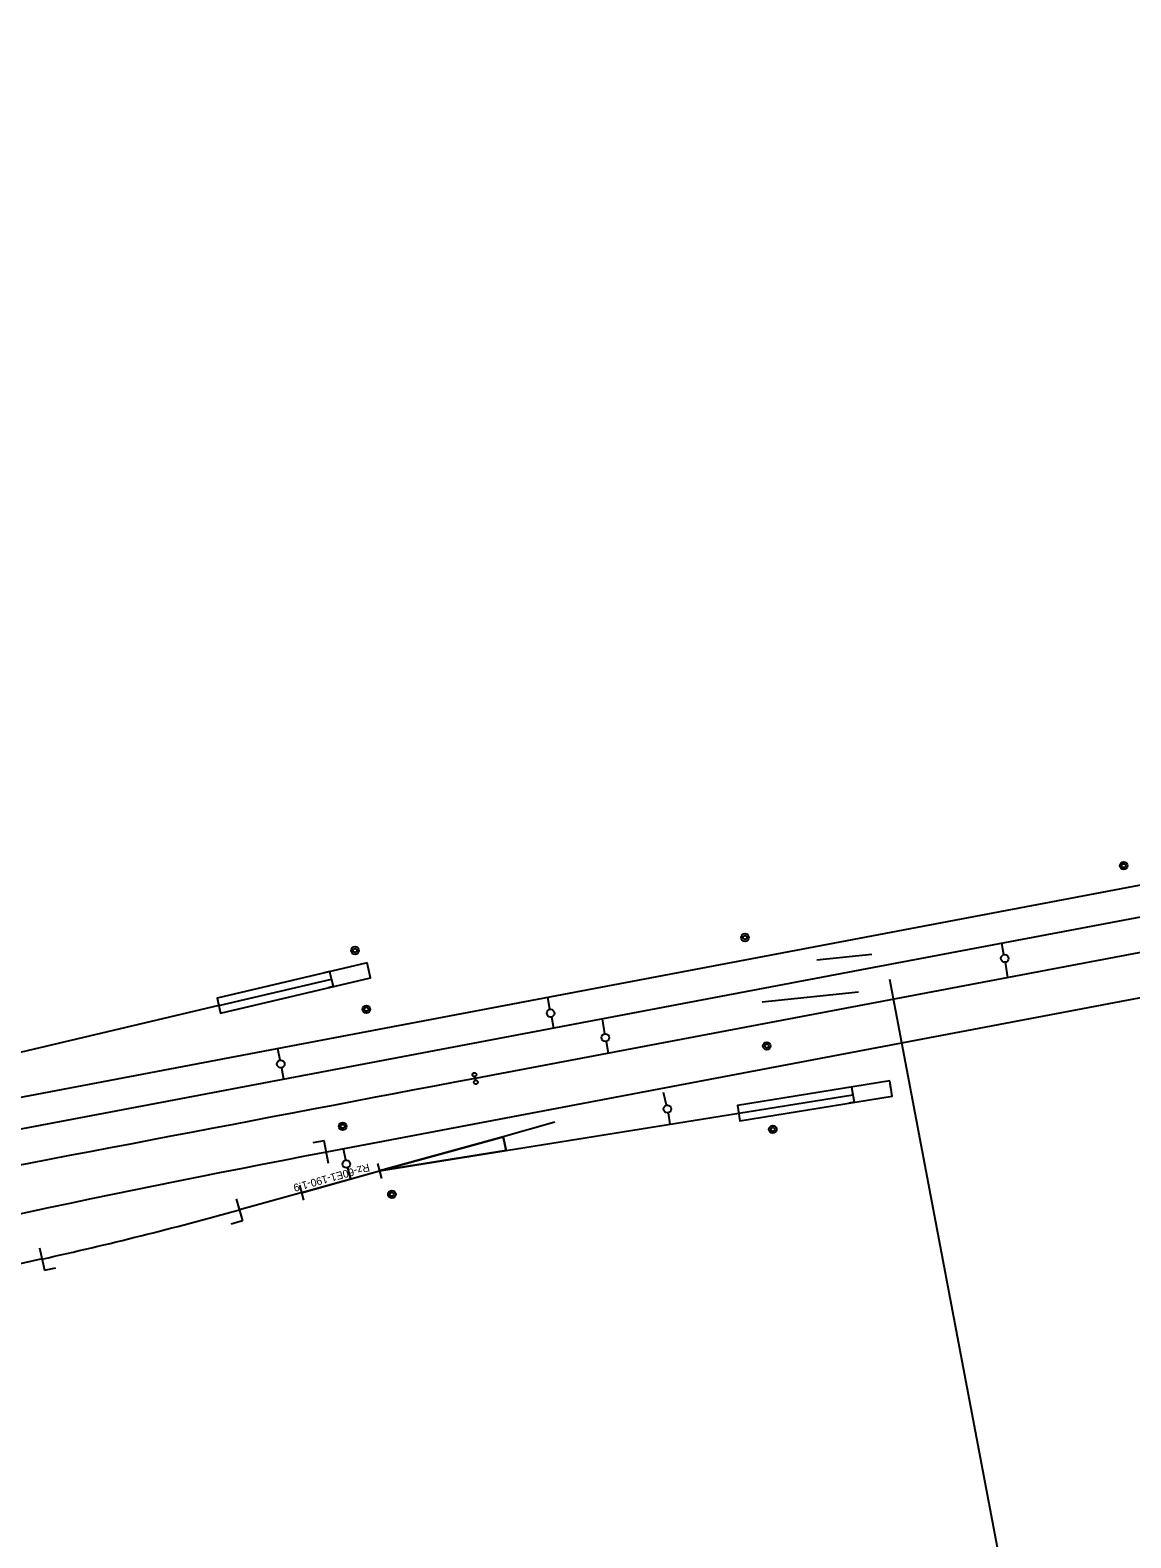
# Model space of a CAD drawing. Extents: x 6540402 to 6566579, y 5525343 to 5532423.
# Drawn here: x 6558463 to 6558605.8, y 5528817.7 to 5529013.3 of the extents above; entities that cross this region are included whole.
import ezdxf

# ---------------------------------------------------------------- set-up
doc = ezdxf.new("R2010")
doc.units = 0
for name, color, linetype in [('IR_ps_geometria', 7, 'Continuous'), ('T_plan_koziol oporowy', 7, 'Continuous'), ('TOR_PS_ODW-studnie betonowe', 7, 'Continuous'), ('TOR_PS_OPIS_T-opisy dodatkowe', 7, 'Continuous'), ('TOR_PS_OPIS_T-symbole geometrii', 7, 'Continuous'), ('TOR_PS_OPIS_T-ukresy', 7, 'Continuous'), ('TOR_PS_T-rozjazdy projektowane', 7, 'Continuous'), ('TOR_PS_T-tory projektowane', 7, 'Continuous'), ('TOR_PS_T-wypelnienia', 7, 'Continuous')]:
    doc.layers.add(name, color=color, linetype=linetype)

# ---------------------------------------------------------------- blocks, each defined once
blk = doc.blocks.new('koziol 15+5')
at = {"layer": 'T_plan_koziol oporowy'}
for p, q in [((15, 1), (14.3, 1)), ((15, 1), (15, -1)), ((20, 0), (20, 1)), ((0, 0), (15, 0)), ((15, -1), (14.3, -1))]:
    blk.add_line(p, q, dxfattribs=at)
blk.add_lwpolyline([(20, 1), (0, 1), (0, -1), (20, -1)], close=True, dxfattribs=at)

msp = doc.modelspace()

# ---------------------------------------------------------------- linework, layer by layer
at = {"layer": 'IR_ps_geometria'}
msp.add_lwpolyline([(6558520.71, 5528877.32), (6558520.76, 5528877.08), (6558520.79, 5528877.08), (6558520.82, 5528877.08), (6558520.86, 5528877.08), (6558520.89, 5528877.07), (6558520.92, 5528877.05), (6558520.95, 5528877.04), (6558520.97, 5528877.02), (6558520.99, 5528876.99), (6558521.01, 5528876.97), (6558521.03, 5528876.94), (6558521.04, 5528876.91), (6558521.05, 5528876.88), (6558521.05, 5528876.85), (6558521.05, 5528876.81), (6558521.05, 5528876.78), (6558521.04, 5528876.75), (6558521.03, 5528876.72), (6558521.01, 5528876.69), (6558520.99, 5528876.66), (6558520.97, 5528876.64), (6558520.94, 5528876.62), (6558520.91, 5528876.61), (6558520.88, 5528876.59), (6558520.85, 5528876.59), (6558520.82, 5528876.58), (6558520.79, 5528876.58), (6558520.75, 5528876.59), (6558520.72, 5528876.6), (6558520.69, 5528876.61), (6558520.66, 5528876.62), (6558520.64, 5528876.64), (6558520.62, 5528876.67), (6558520.6, 5528876.69), (6558520.58, 5528876.72), (6558520.57, 5528876.75), (6558520.56, 5528876.78), (6558520.56, 5528876.82), (6558520.56, 5528876.85), (6558520.56, 5528876.88), (6558520.57, 5528876.91), (6558520.58, 5528876.94), (6558520.6, 5528876.97), (6558520.62, 5528877), (6558520.64, 5528877.02), (6558520.67, 5528877.04), (6558520.7, 5528877.06), (6558520.73, 5528877.07), (6558520.76, 5528877.08), (6558520.67, 5528877.57), (6558520.63, 5528877.56), (6558520.6, 5528877.56), (6558520.57, 5528877.57), (6558520.54, 5528877.58), (6558520.51, 5528877.59), (6558520.48, 5528877.61), (6558520.45, 5528877.63), (6558520.43, 5528877.65), (6558520.41, 5528877.68), (6558520.39, 5528877.7), (6558520.38, 5528877.74), (6558520.37, 5528877.77), (6558520.37, 5528877.8), (6558520.37, 5528877.83), (6558520.37, 5528877.86), (6558520.38, 5528877.9), (6558520.4, 5528877.93), (6558520.41, 5528877.95), (6558520.43, 5528877.98), (6558520.46, 5528878), (6558520.48, 5528878.02), (6558520.51, 5528878.04), (6558520.54, 5528878.05), (6558520.57, 5528878.06), (6558520.6, 5528878.06), (6558520.64, 5528878.06), (6558520.67, 5528878.06), (6558520.7, 5528878.05), (6558520.73, 5528878.04), (6558520.76, 5528878.02), (6558520.79, 5528878), (6558520.81, 5528877.98), (6558520.83, 5528877.95), (6558520.84, 5528877.92), (6558520.86, 5528877.89), (6558520.86, 5528877.86), (6558520.87, 5528877.83), (6558520.87, 5528877.79), (6558520.86, 5528877.76), (6558520.85, 5528877.73), (6558520.84, 5528877.7), (6558520.83, 5528877.67), (6558520.81, 5528877.65), (6558520.78, 5528877.62), (6558520.76, 5528877.6), (6558520.73, 5528877.59), (6558520.7, 5528877.58), (6558520.67, 5528877.57)], close=True, dxfattribs=at)
msp.add_lwpolyline([(6558520.71, 5528877.32), (6558520.76, 5528877.08), (6558520.79, 5528877.08), (6558520.82, 5528877.08), (6558520.86, 5528877.08), (6558520.89, 5528877.07), (6558520.92, 5528877.05), (6558520.95, 5528877.04), (6558520.97, 5528877.02), (6558520.99, 5528876.99), (6558521.01, 5528876.97), (6558521.03, 5528876.94), (6558521.04, 5528876.91), (6558521.05, 5528876.88), (6558521.05, 5528876.85), (6558521.05, 5528876.81), (6558521.05, 5528876.78), (6558521.04, 5528876.75), (6558521.03, 5528876.72), (6558521.01, 5528876.69), (6558520.99, 5528876.66), (6558520.97, 5528876.64), (6558520.94, 5528876.62), (6558520.91, 5528876.61), (6558520.88, 5528876.59), (6558520.85, 5528876.59), (6558520.82, 5528876.58), (6558520.79, 5528876.58), (6558520.75, 5528876.59), (6558520.72, 5528876.6), (6558520.69, 5528876.61), (6558520.66, 5528876.62), (6558520.64, 5528876.64), (6558520.62, 5528876.67), (6558520.6, 5528876.69), (6558520.58, 5528876.72), (6558520.57, 5528876.75), (6558520.56, 5528876.78), (6558520.56, 5528876.82), (6558520.56, 5528876.85), (6558520.56, 5528876.88), (6558520.57, 5528876.91), (6558520.58, 5528876.94), (6558520.6, 5528876.97), (6558520.62, 5528877), (6558520.64, 5528877.02), (6558520.67, 5528877.04), (6558520.7, 5528877.06), (6558520.73, 5528877.07), (6558520.76, 5528877.08), (6558520.67, 5528877.57), (6558520.63, 5528877.56), (6558520.6, 5528877.56), (6558520.57, 5528877.57), (6558520.54, 5528877.58), (6558520.51, 5528877.59), (6558520.48, 5528877.61), (6558520.45, 5528877.63), (6558520.43, 5528877.65), (6558520.41, 5528877.68), (6558520.39, 5528877.7), (6558520.38, 5528877.74), (6558520.37, 5528877.77), (6558520.37, 5528877.8), (6558520.37, 5528877.83), (6558520.37, 5528877.86), (6558520.38, 5528877.9), (6558520.4, 5528877.93), (6558520.41, 5528877.95), (6558520.43, 5528877.98), (6558520.46, 5528878), (6558520.48, 5528878.02), (6558520.51, 5528878.04), (6558520.54, 5528878.05), (6558520.57, 5528878.06), (6558520.6, 5528878.06), (6558520.64, 5528878.06), (6558520.67, 5528878.06), (6558520.7, 5528878.05), (6558520.73, 5528878.04), (6558520.76, 5528878.02), (6558520.79, 5528878), (6558520.81, 5528877.98), (6558520.83, 5528877.95), (6558520.84, 5528877.92), (6558520.86, 5528877.89), (6558520.86, 5528877.86), (6558520.87, 5528877.83), (6558520.87, 5528877.79), (6558520.86, 5528877.76), (6558520.85, 5528877.73), (6558520.84, 5528877.7), (6558520.83, 5528877.67), (6558520.81, 5528877.65), (6558520.78, 5528877.62), (6558520.76, 5528877.6), (6558520.73, 5528877.59), (6558520.7, 5528877.58), (6558520.67, 5528877.57)], close=True, dxfattribs=at)
msp.add_lwpolyline([(6558520.71, 5528877.32), (6558520.76, 5528877.08), (6558520.79, 5528877.08), (6558520.82, 5528877.08), (6558520.86, 5528877.08), (6558520.89, 5528877.07), (6558520.92, 5528877.05), (6558520.95, 5528877.04), (6558520.97, 5528877.02), (6558520.99, 5528876.99), (6558521.01, 5528876.97), (6558521.03, 5528876.94), (6558521.04, 5528876.91), (6558521.05, 5528876.88), (6558521.05, 5528876.85), (6558521.05, 5528876.81), (6558521.05, 5528876.78), (6558521.04, 5528876.75), (6558521.03, 5528876.72), (6558521.01, 5528876.69), (6558520.99, 5528876.66), (6558520.97, 5528876.64), (6558520.94, 5528876.62), (6558520.91, 5528876.61), (6558520.88, 5528876.59), (6558520.85, 5528876.59), (6558520.82, 5528876.58), (6558520.79, 5528876.58), (6558520.75, 5528876.59), (6558520.72, 5528876.6), (6558520.69, 5528876.61), (6558520.66, 5528876.62), (6558520.64, 5528876.64), (6558520.62, 5528876.67), (6558520.6, 5528876.69), (6558520.58, 5528876.72), (6558520.57, 5528876.75), (6558520.56, 5528876.78), (6558520.56, 5528876.82), (6558520.56, 5528876.85), (6558520.56, 5528876.88), (6558520.57, 5528876.91), (6558520.58, 5528876.94), (6558520.6, 5528876.97), (6558520.62, 5528877), (6558520.64, 5528877.02), (6558520.67, 5528877.04), (6558520.7, 5528877.06), (6558520.73, 5528877.07), (6558520.76, 5528877.08), (6558520.67, 5528877.57), (6558520.63, 5528877.56), (6558520.6, 5528877.56), (6558520.57, 5528877.57), (6558520.54, 5528877.58), (6558520.51, 5528877.59), (6558520.48, 5528877.61), (6558520.45, 5528877.63), (6558520.43, 5528877.65), (6558520.41, 5528877.68), (6558520.39, 5528877.7), (6558520.38, 5528877.74), (6558520.37, 5528877.77), (6558520.37, 5528877.8), (6558520.37, 5528877.83), (6558520.37, 5528877.86), (6558520.38, 5528877.9), (6558520.4, 5528877.93), (6558520.41, 5528877.95), (6558520.43, 5528877.98), (6558520.46, 5528878), (6558520.48, 5528878.02), (6558520.51, 5528878.04), (6558520.54, 5528878.05), (6558520.57, 5528878.06), (6558520.6, 5528878.06), (6558520.64, 5528878.06), (6558520.67, 5528878.06), (6558520.7, 5528878.05), (6558520.73, 5528878.04), (6558520.76, 5528878.02), (6558520.79, 5528878), (6558520.81, 5528877.98), (6558520.83, 5528877.95), (6558520.84, 5528877.92), (6558520.86, 5528877.89), (6558520.86, 5528877.86), (6558520.87, 5528877.83), (6558520.87, 5528877.79), (6558520.86, 5528877.76), (6558520.85, 5528877.73), (6558520.84, 5528877.7), (6558520.83, 5528877.67), (6558520.81, 5528877.65), (6558520.78, 5528877.62), (6558520.76, 5528877.6), (6558520.73, 5528877.59), (6558520.7, 5528877.58), (6558520.67, 5528877.57)], close=True, dxfattribs=at)
msp.add_lwpolyline([(6558520.71, 5528877.32), (6558520.76, 5528877.08), (6558520.79, 5528877.08), (6558520.82, 5528877.08), (6558520.86, 5528877.08), (6558520.89, 5528877.07), (6558520.92, 5528877.05), (6558520.95, 5528877.04), (6558520.97, 5528877.02), (6558520.99, 5528876.99), (6558521.01, 5528876.97), (6558521.03, 5528876.94), (6558521.04, 5528876.91), (6558521.05, 5528876.88), (6558521.05, 5528876.85), (6558521.05, 5528876.81), (6558521.05, 5528876.78), (6558521.04, 5528876.75), (6558521.03, 5528876.72), (6558521.01, 5528876.69), (6558520.99, 5528876.66), (6558520.97, 5528876.64), (6558520.94, 5528876.62), (6558520.91, 5528876.61), (6558520.88, 5528876.59), (6558520.85, 5528876.59), (6558520.82, 5528876.58), (6558520.79, 5528876.58), (6558520.75, 5528876.59), (6558520.72, 5528876.6), (6558520.69, 5528876.61), (6558520.66, 5528876.62), (6558520.64, 5528876.64), (6558520.62, 5528876.67), (6558520.6, 5528876.69), (6558520.58, 5528876.72), (6558520.57, 5528876.75), (6558520.56, 5528876.78), (6558520.56, 5528876.82), (6558520.56, 5528876.85), (6558520.56, 5528876.88), (6558520.57, 5528876.91), (6558520.58, 5528876.94), (6558520.6, 5528876.97), (6558520.62, 5528877), (6558520.64, 5528877.02), (6558520.67, 5528877.04), (6558520.7, 5528877.06), (6558520.73, 5528877.07), (6558520.76, 5528877.08), (6558520.67, 5528877.57), (6558520.63, 5528877.56), (6558520.6, 5528877.56), (6558520.57, 5528877.57), (6558520.54, 5528877.58), (6558520.51, 5528877.59), (6558520.48, 5528877.61), (6558520.45, 5528877.63), (6558520.43, 5528877.65), (6558520.41, 5528877.68), (6558520.39, 5528877.7), (6558520.38, 5528877.74), (6558520.37, 5528877.77), (6558520.37, 5528877.8), (6558520.37, 5528877.83), (6558520.37, 5528877.86), (6558520.38, 5528877.9), (6558520.4, 5528877.93), (6558520.41, 5528877.95), (6558520.43, 5528877.98), (6558520.46, 5528878), (6558520.48, 5528878.02), (6558520.51, 5528878.04), (6558520.54, 5528878.05), (6558520.57, 5528878.06), (6558520.6, 5528878.06), (6558520.64, 5528878.06), (6558520.67, 5528878.06), (6558520.7, 5528878.05), (6558520.73, 5528878.04), (6558520.76, 5528878.02), (6558520.79, 5528878), (6558520.81, 5528877.98), (6558520.83, 5528877.95), (6558520.84, 5528877.92), (6558520.86, 5528877.89), (6558520.86, 5528877.86), (6558520.87, 5528877.83), (6558520.87, 5528877.79), (6558520.86, 5528877.76), (6558520.85, 5528877.73), (6558520.84, 5528877.7), (6558520.83, 5528877.67), (6558520.81, 5528877.65), (6558520.78, 5528877.62), (6558520.76, 5528877.6), (6558520.73, 5528877.59), (6558520.7, 5528877.58), (6558520.67, 5528877.57)], close=True, dxfattribs=at)
at = {"layer": 'TOR_PS_ODW-studnie betonowe'}
for centre, radius in [((6558604.86, 5528904.93), 0.5), ((6558604.86, 5528904.93), 0.25), ((6558555.73, 5528895.61), 0.5), ((6558555.73, 5528895.61), 0.25), ((6558505.13, 5528893.92), 0.5), ((6558505.13, 5528893.92), 0.25), ((6558506.6, 5528886.3), 0.5), ((6558506.6, 5528886.3), 0.25), ((6558558.55, 5528881.54), 0.5), ((6558558.55, 5528881.54), 0.25), ((6558503.53, 5528871.11), 0.5), ((6558503.53, 5528871.11), 0.25), ((6558559.33, 5528870.71), 0.5), ((6558559.33, 5528870.71), 0.25), ((6558509.91, 5528862.29), 0.5), ((6558509.91, 5528862.29), 0.25)]:
    msp.add_circle(centre, radius, dxfattribs=at)
at = {"layer": 'TOR_PS_OPIS_T-opisy dodatkowe'}
msp.add_line((6558741.9, 5528007.05), (6558574.5, 5528890.18), dxfattribs=at)
at = {"layer": 'TOR_PS_OPIS_T-symbole geometrii'}
for p, q in [((6558501.13, 5528869.23), (6558499.66, 5528868.95)), ((6558501.69, 5528866.29), (6558501.13, 5528869.23)), ((6558489.73, 5528861.72), (6558490.53, 5528858.83)), ((6558490.53, 5528858.83), (6558489.08, 5528858.43)), ((6558464.2, 5528855.36), (6558464.85, 5528852.43)), ((6558464.85, 5528852.43), (6558466.32, 5528852.76))]:
    msp.add_line(p, q, dxfattribs=at)
at = {"layer": 'TOR_PS_OPIS_T-ukresy'}
for p, q in [((6558589.32, 5528893.38), (6558589.04, 5528894.85)), ((6558589.49, 5528892.39), (6558589.77, 5528890.41)), ((6558530.42, 5528886.29), (6558530.15, 5528887.81)), ((6558530.6, 5528885.3), (6558530.88, 5528883.83)), ((6558537.54, 5528883.12), (6558537.25, 5528885.04)), ((6558537.7, 5528882.13), (6558537.99, 5528880.6)), ((6558495.41, 5528879.7), (6558495.13, 5528881.17)), ((6558495.59, 5528878.72), (6558495.85, 5528877.23)), ((6558545.54, 5528873.85), (6558545.13, 5528875.52)), ((6558545.74, 5528872.87), (6558545.98, 5528871.39)), ((6558503.92, 5528866.7), (6558503.64, 5528868.18)), ((6558504.15, 5528865.73), (6558504.55, 5528864.27))]:
    msp.add_line(p, q, dxfattribs=at)
for centre in [(6558589.42, 5528892.89), (6558530.5, 5528885.79), (6558537.61, 5528882.62), (6558495.5, 5528879.21), (6558545.66, 5528873.36), (6558504.01, 5528866.21)]:
    msp.add_circle(centre, 0.5, dxfattribs=at)
at = {"layer": 'TOR_PS_T-rozjazdy projektowane'}
for p, q in [((6558508.32, 5528865.32), (6558524.33, 5528869.76)), ((6558524.33, 5528869.76), (6558524.72, 5528867.96)), ((6558524.72, 5528867.96), (6558508.32, 5528865.32)), ((6558498.18, 5528862.5), (6558508.32, 5528865.32)), ((6558508.05, 5528866.28), (6558508.58, 5528864.35)), ((6558497.91, 5528863.47), (6558498.44, 5528861.54))]:
    msp.add_line(p, q, dxfattribs=at)
at = {"layer": 'TOR_PS_T-tory projektowane'}
for p, q in [((6560357.98, 5529234.28), (6558563.91, 5528894.21)), ((6558913.74, 5528945.92), (6558501.41, 5528867.76)), ((6558654.18, 5528902.62), (6558520.71, 5528877.32)), ((6558612.41, 5528899.28), (6558571.55, 5528891.54)), ((6558563.91, 5528894.21), (6558523.04, 5528886.47)), ((6558572.17, 5528893.42), (6558565.04, 5528892.67)), ((6558571.55, 5528891.54), (6557352.88, 5528660.54)), ((6558570.46, 5528888.51), (6558557.94, 5528887.2)), ((6558487.46, 5528886.77), (6558443.64, 5528876.44)), ((6558523.04, 5528886.47), (6558498.4, 5528881.8)), ((6558498.4, 5528881.8), (6558457.42, 5528874.03)), ((6558524.72, 5528867.96), (6558554.91, 5528872.83)), ((6558531.07, 5528871.63), (6558524.33, 5528869.76)), ((6558524.33, 5528869.76), (6558498.18, 5528862.5)), ((6558498.26, 5528862.53), (6558490.13, 5528860.27)), ((6558464.53, 5528853.9), (6558317.16, 5528821.3))]:
    msp.add_line(p, q, dxfattribs=at)
for centre, radius, start, end in [((6564657.21, 5496503.79), 32950, 100.733239, 100.882278), ((6558820.81, 5527182.76), 1715, 100.73324, 103.75581), ((6558356.53, 5529342.09), 500, 282.4733, 285.4969)]:
    msp.add_arc(centre, radius, start, end, dxfattribs=at)
at = {"layer": 'TOR_PS_T-wypelnienia'}
msp.add_lwpolyline([(6558524.72, 5528867.96), (6558524.33, 5528869.76), (6558508.32, 5528865.32), (6558524.72, 5528867.96)], dxfattribs=at)

# ---------------------------------------------------------------- block references
at = {"layer": 'T_plan_koziol oporowy'}
for p, rotation in [((6558487.46, 5528886.77), 13.266871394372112), ((6558554.91, 5528872.83), 9.156690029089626)]:
    msp.add_blockref('koziol 15+5', p, dxfattribs=dict(at, rotation=rotation))

# ---------------------------------------------------------------- texts
at = {"layer": 'TOR_PS_T-rozjazdy projektowane'}
msp.add_text('Rz-60E1-190-1:9', height=1, rotation=195.4969, dxfattribs=at).set_placement((6558506.86, 5528866.29))

doc.saveas('drawing.dxf')
